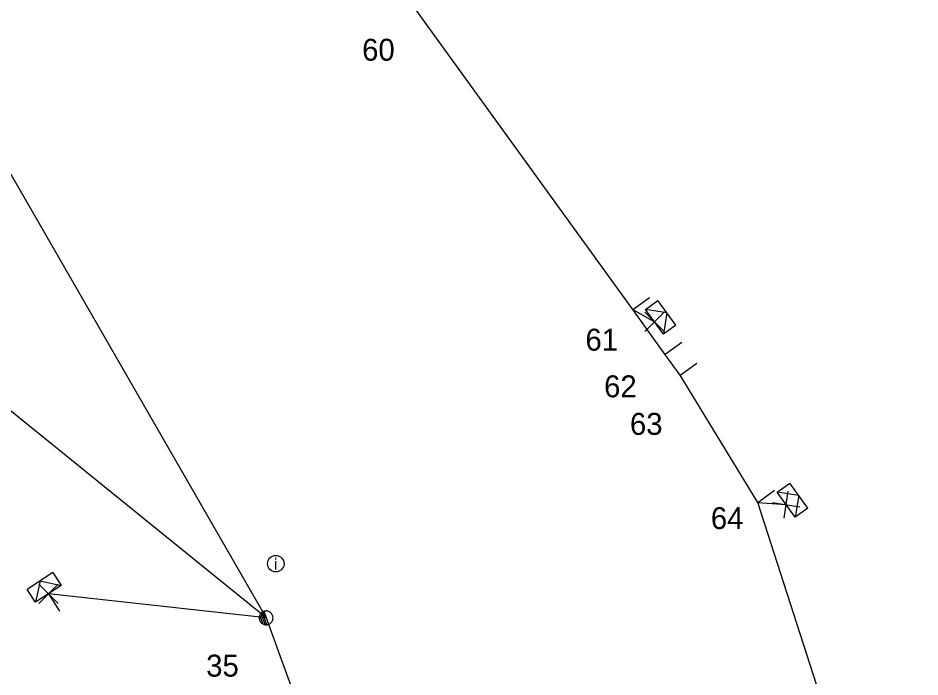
# Model space of a CAD drawing. Extents: x -536148 to -535465, y -1201639 to -1201298.
# Drawn here: x -535581.57 to -535540.44, y -1201523.39 to -1201493.36 of the extents above; entities that cross this region are included whole.
import ezdxf

# ---------------------------------------------------------------- set-up
doc = ezdxf.new("R2010")
doc.units = 0
for name, color, linetype in [('CIZÍ_NADZEM_POPIS', 7, 'Continuous'), ('CIZÍ_PODZEM', 7, 'Continuous'), ('CIZÍ_PODZEM_POPIS', 7, 'Continuous'), ('DOPLŇ_POPISY', 7, 'Continuous'), ('ELE_EON', 7, 'Continuous'), ('ELE_EON_POPIS', 7, 'Continuous'), ('KN_VKP_HRAN_NEZNATELNÁ', 7, 'Continuous'), ('KN_VKP_HRAN_SPORNÁ', 7, 'Continuous'), ('NADZEM_NN_IZOL_POPIS', 7, 'Continuous'), ('PB_NN_POPIS', 7, 'Continuous'), ('PK_HRAN_POHYBLIVÁ', 7, 'Continuous'), ('PLG_EXPORT_GPE', 7, 'Continuous')]:
    doc.layers.add(name, color=color, linetype=linetype)

# ---------------------------------------------------------------- blocks, each defined once
blk = doc.blocks.new('NN440')
at = {"layer": 'ELE_EON_POPIS'}
for points in [[(0.631, -0.004), (0.627, 0.062), (0.617, 0.127), (0.6, 0.191), (0.577, 0.252), (0.547, 0.311), (0.511, 0.366), (0.469, 0.417), (0.423, 0.464), (0.371, 0.505), (0.316, 0.542), (0.257, 0.571), (0.196, 0.595), (0.132, 0.612), (0.067, 0.622), (0.001, 0.626), (-0.065, 0.622), (-0.13, 0.612), (-0.194, 0.595), (-0.255, 0.571), (-0.314, 0.542), (-0.369, 0.505), (-0.42, 0.464), (-0.467, 0.417), (-0.509, 0.366), (-0.544, 0.311), (-0.574, 0.252), (-0.598, 0.191), (-0.615, 0.127), (-0.626, 0.062), (-0.629, -0.004), (-0.626, -0.07), (-0.615, -0.135), (-0.598, -0.199), (-0.574, -0.26), (-0.544, -0.319), (-0.509, -0.374), (-0.467, -0.426), (-0.42, -0.472), (-0.369, -0.514), (-0.314, -0.55), (-0.255, -0.58), (-0.194, -0.603), (-0.13, -0.62), (-0.065, -0.631), (0.001, -0.634), (0.067, -0.631), (0.132, -0.62), (0.196, -0.603), (0.257, -0.58), (0.316, -0.55), (0.371, -0.514), (0.423, -0.472), (0.469, -0.426), (0.511, -0.374), (0.547, -0.319), (0.577, -0.26), (0.6, -0.199), (0.617, -0.135), (0.627, -0.07), (0.631, -0.004)], [(-0.631, 0), (0.629, 0)], [(-0.601, -0.177), (0.57, -0.177)], [(-0.513, -0.325), (0.501, -0.325)], [(-0.375, -0.473), (0.353, -0.473)]]:
    blk.add_lwpolyline(points, dxfattribs=at)
blk = doc.blocks.new('NN770')
at = {"layer": 'CIZÍ_PODZEM_POPIS'}
for p, q in [((0.002, 0.187), (0.002, 0.263)), ((0.002, -0.276), (0.002, 0.111))]:
    blk.add_line(p, q, dxfattribs=at)
blk.add_circle((0, -0.008), 0.375, dxfattribs=at)
blk = doc.blocks.new('NN800')
at = {"layer": 'ELE_EON'}
for points in [[(-0.442, 0.442), (0.442, -0.442)], [(-0.442, -0.442), (0.442, 0.442)]]:
    blk.add_lwpolyline(points, dxfattribs=at)
blk = doc.blocks.new('NN630')
at = {"layer": 'CIZÍ_PODZEM'}
for points in [[(-0.003, -0.7), (-0.703, 0)], [(-0.703, -0.7), (-0.703, 0), (0.697, 0), (0.697, -0.7)], [(-0.003, -0.7), (0.697, 0)], [(-0.703, -0.7), (0.697, -0.7)]]:
    blk.add_lwpolyline(points, dxfattribs=at)
blk = doc.blocks.new('NN510')
at = {"layer": 'ELE_EON_POPIS'}
blk.add_lwpolyline([(0.001, 0.002), (0.001, 0.939)], dxfattribs=at)

msp = doc.modelspace()

# ---------------------------------------------------------------- linework, layer by layer
at = {"layer": 'CIZÍ_NADZEM_POPIS'}
msp.add_lwpolyline([(-535553.538, -1201506.643), (-535552.546, -1201507.204)], dxfattribs=at)
at = {"layer": 'ELE_EON'}
msp.add_lwpolyline([(-535704.28, -1201335.78), (-535687.29, -1201370.27), (-535663.05, -1201399.63), (-535635.32, -1201433.41), (-535614.862, -1201457.774), (-535589.24, -1201487.744), (-535570.255, -1201520.699), (-535562.055, -1201543.241)], dxfattribs=at)
at = {"layer": 'NADZEM_NN_IZOL_POPIS'}
msp.add_lwpolyline([(-535540.439, -1201538.364), (-535540.519, -1201538.116), (-535547.83, -1201515.436), (-535551.375, -1201509.636), (-535552.066, -1201508.681), (-535553.538, -1201506.643), (-535563.322, -1201493.118), (-535566.21, -1201489.133)], dxfattribs=at)
at = {"layer": 'PB_NN_POPIS'}
for points in [[(-535570.255, -1201520.699), (-535587.383, -1201506.844)], [(-535547.831, -1201515.436), (-535546.538, -1201515.538)], [(-535570.255, -1201520.699), (-535580.184, -1201519.608)]]:
    msp.add_lwpolyline(points, dxfattribs=at)

# ---------------------------------------------------------------- block references
at = {"layer": 'DOPLŇ_POPISY'}
for p, rotation in [((-535553.539, -1201506.643), -54.1297111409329), ((-535552.067, -1201508.681), -54.14577773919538), ((-535551.376, -1201509.636), -54.15740823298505), ((-535547.832, -1201515.436), -54.16792219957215), ((-535580.183, -1201519.607), -146.90289160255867)]:
    msp.add_blockref('NN510', p, dxfattribs=dict(at, rotation=rotation))
at = {"layer": 'DOPLŇ_POPISY', "xscale": 0.5, "yscale": 0.5000000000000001, "rotation": -70.02306397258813}
msp.add_blockref('NN440', (-535570.255, -1201520.699), dxfattribs=at)
at = {"layer": 'KN_VKP_HRAN_NEZNATELNÁ'}
for p in [(-535552.546, -1201507.204), (-535580.184, -1201519.608)]:
    msp.add_blockref('NN800', p, dxfattribs=at)
at = {"layer": 'KN_VKP_HRAN_NEZNATELNÁ', "rotation": 36.23112518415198}
msp.add_blockref('NN800', (-535546.538, -1201515.538), dxfattribs=at)
at = {"layer": 'KN_VKP_HRAN_SPORNÁ'}
for p, rotation in [((-535552.546, -1201507.204), 125.85844165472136), ((-535546.538, -1201515.537), 125.86110827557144), ((-535580.184, -1201519.608), -146.90289173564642)]:
    msp.add_blockref('NN630', p, dxfattribs=dict(at, rotation=rotation))
at = {"layer": 'PK_HRAN_POHYBLIVÁ'}
msp.add_blockref('NN770', (-535569.815, -1201518.224), dxfattribs=at)

# ---------------------------------------------------------------- texts
at = {"layer": 'PLG_EXPORT_GPE'}
for s, p in [('60', (-535565.878, -1201495.308)), ('61', (-535555.694, -1201508.522)), ('62', (-535554.844, -1201510.648)), ('63', (-535553.665, -1201512.36)), ('64', (-535549.975, -1201516.654)), ('35', (-535572.989, -1201523.379))]:
    msp.add_text(s, height=1, dxfattribs=at).set_placement(p)

doc.saveas('drawing.dxf')
